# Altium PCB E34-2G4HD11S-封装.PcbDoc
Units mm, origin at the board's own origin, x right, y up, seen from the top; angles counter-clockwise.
Board outline 20.02 x 12 mm, 2 copper layers (Top Layer, Bottom Layer); 2 components, 38 nets, 9 pads, 0 vias.
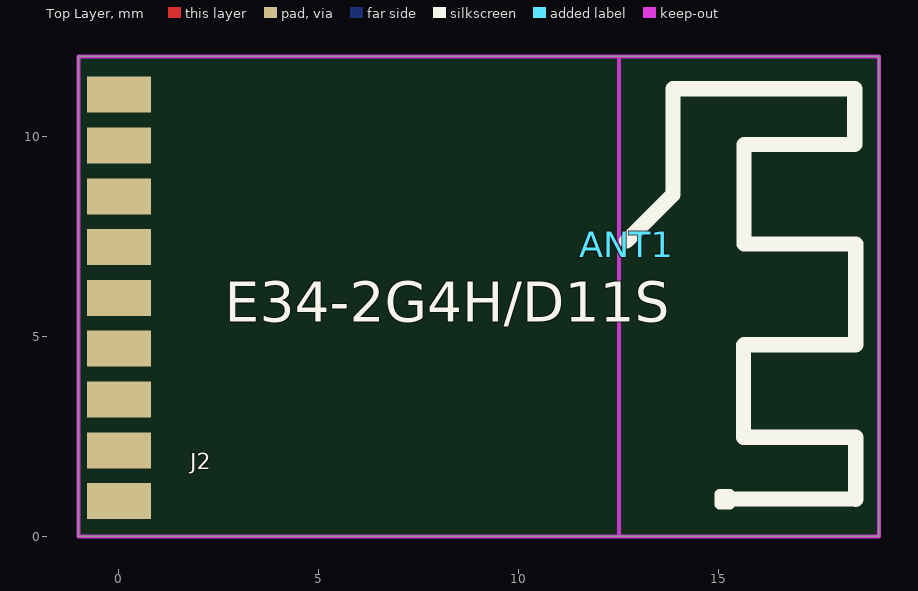
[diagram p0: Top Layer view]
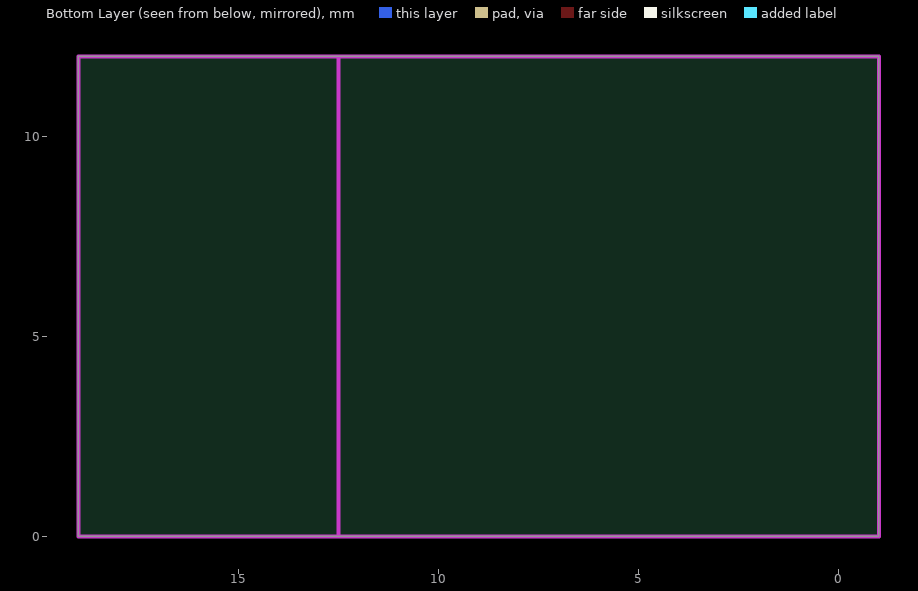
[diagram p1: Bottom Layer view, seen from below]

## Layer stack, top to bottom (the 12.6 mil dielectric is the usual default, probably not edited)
Top Solder: solder mask 0.0102, Solder Resist, Dk 3.5
Top Layer: signal copper 0.0356
Dielectric 1: dielectric 0.32, FR-4, Dk 4.8
Bottom Layer: signal copper 0.0356
Bottom Solder: solder mask 0.0102, Solder Resist, Dk 3.5

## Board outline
-1.016,0 -1.016,12 19,12 19,0

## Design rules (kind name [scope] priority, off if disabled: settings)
Clearance Clearance_1 [InPolygon] p1: gap=0.3
Clearance [All] p2: gap=0.16
PlaneConnect [All] p1: planeconnectstyle=Direct reliefexpansion=0.508 reliefentries=4 reliefconductorwidth=0.254 reliefairgap=0.254
PolygonConnect [All] p1: connectstyle=Direct reliefconductorwidth=0.254 reliefentries=4 polygonreliefangle="90 Angle" airgapwidth=0.254
RoutingVias [All] p1: holewidth=0.711 width=1.27 viastyle="Through Hole" minholewidth=0.711 minwidth=1.27 maxholewidth=0.711 maxwidth=1.27
SolderMaskExpansion [All] p1: expansion=0.102
Width [All] p1: maxlimit=3 minlimit=0.16 preferedwidth=0.254
29 further rules are at their usual default settings.

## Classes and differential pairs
component class 24V-12V: *1
component class E34-2G410S: J2

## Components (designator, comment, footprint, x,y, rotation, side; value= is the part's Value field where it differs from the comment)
ANT1 "IPEX" E-ANT-2.4G-1 12.7,7.29 r90 top
J2 "PIN" E-9P-1.27-9 0,11.04 r270 top

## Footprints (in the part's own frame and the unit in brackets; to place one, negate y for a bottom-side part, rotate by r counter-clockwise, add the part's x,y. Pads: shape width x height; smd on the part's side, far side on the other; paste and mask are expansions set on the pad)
E-9P-1.27-9 [mm]
  rect 0.9x1.6 smd: 1(0,0) 2(1.27,0) 3(2.54,0) 4(3.81,0) 5(5.08,0) 6(6.35,0) 7(7.62,0) 8(8.89,0) 9(10.16,0)
E-ANT-2.4G-1 [mm]
  silkscreen extent -6.49,-5.72 3.9,0.01

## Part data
ANT1: library part ANT-SMA

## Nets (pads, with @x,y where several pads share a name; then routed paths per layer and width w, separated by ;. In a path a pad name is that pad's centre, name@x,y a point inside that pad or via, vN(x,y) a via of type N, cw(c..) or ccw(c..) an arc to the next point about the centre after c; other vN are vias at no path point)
3.3V: 
AUX: 
AUX1: 
CSN: 
DATA: 
GND: 
M00: 
M0: 
M1: 
M11: 
MISO: 
MOSI: 
Net*1_1: 
Net*1_2: 
Net*1_3: 
Net*1_5: 
Net*1_6: 
Net*1_7: 
NetANT1_1: 
NetC2_1: 
NetC6_1: 
NetC8_1: 
NetC9_1: 
NetR6_2: 
NetR9_1: 
P1.5: 
P15: 
RESET: 
RX: 
SCK: 
SWCLK: 
SWDIO: 
TX: 
UART0_RXD: 
UART0_TXD: 
VCC: 
VCC_3V3: 
VOT: 
pads on no net: J2.1 J2.2 J2.3 J2.4 J2.5 J2.6 J2.7 J2.8 J2.9

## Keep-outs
Keep-Out Layer:
  lines w0.1: 12.497,0 12.497,12 13,12
  lines w0.102: 12.497,0 13.259,0 ; 12.675,12 13.259,12 ; -1.016,0 -1.016,12 19,12 19,0 -1.016,0

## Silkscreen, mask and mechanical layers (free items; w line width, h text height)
Top Overlay:
  text "E34-2G4H/D11S" at 2.642,5.359 h1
